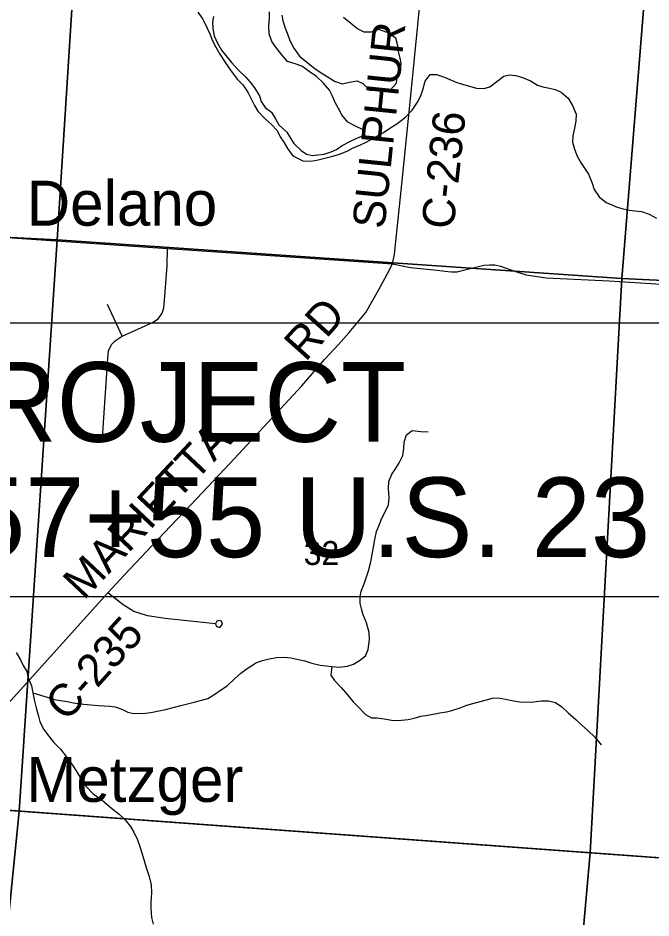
# Model space of a CAD drawing. Extents: x 0 to 34, y 0 to 22.
# Drawn here: x 6.672 to 7.784, y 18.22 to 19.8 of the extents above; entities that cross this region are included whole.
import ezdxf

# ---------------------------------------------------------------- set-up
doc = ezdxf.new("R2010")
doc.units = 0
for name, color, linetype in [('GM_X_Corporation', 7, 'Continuous'), ('GM_X_County_Road', 7, 'Continuous'), ('GM_X_County_Road_Text', 7, 'Continuous'), ('GM_X_Minor_Lake', 7, 'Continuous'), ('GM_X_Minor_River', 7, 'Continuous'), ('GM_X_Section_Text', 7, 'Continuous'), ('GM_X_Township_Road', 7, 'Continuous'), ('GM_X_Unincorporated_Text', 7, 'Continuous'), ('SH_Text', 7, 'Continuous')]:
    doc.layers.add(name, color=color, linetype=linetype)

msp = doc.modelspace()

# ---------------------------------------------------------------- linework, layer by layer
at = {"layer": 'GM_X_Corporation'}
for points in [[(5.8125, 20.4147), (5.8133, 20.4283), (6.802, 20.3679), (6.741, 19.4109), (5.7537, 19.4608)], [(6.802, 20.3679), (7.8088, 20.2797), (7.7331, 19.3433), (6.741, 19.4109)], [(7.8088, 20.2797), (8.8059, 20.2218), (8.7529, 19.294), (7.7331, 19.3433)], [(5.7537, 19.4608), (6.741, 19.4109), (6.6744, 18.4075), (5.6796, 18.4816)], [(6.741, 19.4109), (7.7331, 19.3433), (7.6778, 18.3345), (6.6744, 18.4075)], [(7.7331, 19.3433), (8.7529, 19.294), (8.6957, 18.2606), (7.6778, 18.3345)], [(5.6796, 18.4816), (6.6744, 18.4075), (6.5737, 17.4057), (5.601, 17.4809)], [(6.6744, 18.4075), (7.6778, 18.3345), (7.5885, 17.3345), (6.5737, 17.4057)], [(7.6778, 18.3345), (8.6957, 18.2606), (8.5882, 17.2585), (7.5885, 17.3345)]]:
    msp.add_lwpolyline(points, close=True, dxfattribs=at)
for points in [[(8.9, 18.2459), (6.4848, 18.4217), (6.0623, 18.451), (6.0209, 18.4538), (5.9218, 18.4615), (5.8252, 18.4693), (5.7826, 18.4727), (5.7687, 18.4738), (5.7047, 18.479), (5.6707, 18.4817), (5.1903, 18.5127), (5.1284, 18.4671)], [(6.4848, 18.4217), (8.9, 18.2459)]]:
    msp.add_lwpolyline(points, dxfattribs=at)
at = {"layer": 'GM_X_County_Road'}
msp.add_line((7.2681, 19.265), (7.2835, 19.2833), dxfattribs=at)
for points in [[(7.3304, 19.3689), (7.3338, 19.386), (7.3468, 19.5088), (7.3626, 19.6642), (7.3815, 19.8538), (7.4091, 20.1111), (7.4196, 20.2137), (7.4445, 20.4597), (7.4584, 20.5745), (7.4672, 20.6478), (7.474, 20.7219), (7.4739, 20.7892), (7.4713, 20.8345), (7.4616, 20.8801), (7.4574, 20.9)], [(6.4885, 18.4248), (6.6139, 18.5525), (6.6769, 18.6211), (6.8299, 18.7909), (6.8595, 18.823), (6.9179, 18.8845), (6.9863, 18.9569), (7.0524, 19.0267), (7.1182, 19.0976), (7.1707, 19.1546), (7.211, 19.201), (7.2355, 19.2269), (7.254, 19.2481), (7.2835, 19.2833), (7.3058, 19.3225), (7.3211, 19.3507), (7.3304, 19.3689)], [(7.3304, 19.3689), (7.3619, 19.3621), (7.4086, 19.3579), (7.4272, 19.3554), (7.4341, 19.355), (7.444, 19.3549), (7.4573, 19.3582), (7.4905, 19.3662), (7.5008, 19.3673), (7.5099, 19.3672), (7.5201, 19.3648), (7.5448, 19.3559), (7.5652, 19.3496), (7.6002, 19.3443), (7.7112, 19.3388), (7.9024, 19.3267)]]:
    msp.add_lwpolyline(points, dxfattribs=at)
at = {"layer": 'GM_X_Minor_Lake'}
for points in [[(7.016, 19.8028), (7.0141, 19.7933), (7.0145, 19.7822), (7.0171, 19.7693), (7.0228, 19.7564), (7.0296, 19.7442), (7.0372, 19.7347), (7.0474, 19.7221), (7.0588, 19.7096), (7.0717, 19.6974), (7.08, 19.6875), (7.0876, 19.678), (7.0967, 19.6635), (7.0993, 19.6536), (7.1065, 19.6434), (7.1179, 19.635), (7.1244, 19.6232), (7.1304, 19.6129), (7.1444, 19.6), (7.1509, 19.5893), (7.1569, 19.5798), (7.1695, 19.5676), (7.1793, 19.5615), (7.1892, 19.5592), (7.1998, 19.56), (7.2101, 19.5615), (7.2226, 19.5653), (7.2321, 19.5694), (7.2416, 19.5766), (7.2553, 19.5838), (7.2667, 19.5888), (7.2793, 19.5941), (7.2789, 19.6039), (7.2652, 19.6104), (7.2516, 19.6177), (7.2414, 19.6306), (7.2353, 19.6413), (7.2296, 19.6523), (7.2247, 19.6633), (7.2194, 19.6736), (7.2092, 19.6861), (7.1966, 19.6976), (7.1837, 19.7063), (7.1709, 19.7158), (7.1591, 19.7197), (7.1458, 19.7239), (7.1356, 19.736), (7.125, 19.7494), (7.1185, 19.7593), (7.1136, 19.7729), (7.1129, 19.7862), (7.114, 19.7995), (7.1144, 19.8113)], [(7.1361, 19.8052), (7.1376, 19.7953), (7.1417, 19.7828), (7.1466, 19.7706), (7.15, 19.7611), (7.1569, 19.7474), (7.1671, 19.7333), (7.1796, 19.723), (7.1936, 19.7116), (7.2031, 19.7055), (7.2153, 19.6979), (7.2285, 19.6895), (7.2418, 19.6849), (7.2547, 19.6876), (7.268, 19.6898), (7.2779, 19.6856), (7.2904, 19.6735), (7.3007, 19.6731), (7.3136, 19.6723), (7.3261, 19.6738), (7.3375, 19.6859), (7.3383, 19.6962), (7.3444, 19.7095), (7.3452, 19.7205), (7.3437, 19.73), (7.341, 19.7418), (7.3395, 19.7513), (7.3361, 19.765), (7.3206, 19.7749), (7.3062, 19.7802), (7.2925, 19.7753), (7.2807, 19.7757), (7.2689, 19.7814), (7.2568, 19.7909), (7.2443, 19.8012)]]:
    msp.add_lwpolyline(points, dxfattribs=at)
at = {"layer": 'GM_X_Minor_River'}
for p, q in [((7.2733, 18.7725), (7.2733, 18.784)), ((7.2756, 18.763), (7.2733, 18.7725)), ((7.279, 18.7527), (7.2756, 18.763))]:
    msp.add_line(p, q, dxfattribs=at)
for points in [[(6.9883, 19.8104), (6.997, 19.7982), (7.0046, 19.7826), (7.0095, 19.7727), (7.0137, 19.7606), (7.0197, 19.7492), (7.0269, 19.737), (7.0345, 19.7252), (7.0425, 19.713), (7.0501, 19.7024), (7.058, 19.6925), (7.0675, 19.683), (7.0762, 19.6704), (7.0879, 19.6468), (7.0936, 19.6366), (7.1061, 19.624), (7.1175, 19.6133), (7.1274, 19.6031), (7.1327, 19.592), (7.1391, 19.5825), (7.1455, 19.5715), (7.1554, 19.5582), (7.1725, 19.5498), (7.1869, 19.549), (7.1994, 19.5516), (7.2158, 19.5554), (7.2257, 19.558), (7.2374, 19.5614), (7.2504, 19.5667), (7.2599, 19.572), (7.2743, 19.5777), (7.2842, 19.5823), (7.2998, 19.591), (7.3142, 19.5993), (7.3275, 19.608), (7.3378, 19.6145), (7.353, 19.6262), (7.3648, 19.6384), (7.3739, 19.6528), (7.3797, 19.6627), (7.3835, 19.6741), (7.3877, 19.6896), (7.3964, 19.701), (7.4074, 19.7014), (7.4215, 19.6968), (7.431, 19.6922), (7.4431, 19.6873), (7.4534, 19.6842), (7.4632, 19.6815), (7.4777, 19.6773), (7.491, 19.6765), (7.5012, 19.6796), (7.5138, 19.689), (7.5259, 19.6981), (7.5354, 19.7004), (7.5468, 19.6996), (7.5586, 19.6958), (7.5726, 19.6901), (7.5848, 19.6825), (7.5946, 19.6794), (7.6064, 19.6771), (7.6159, 19.6748), (7.6265, 19.6699), (7.6387, 19.6596), (7.6466, 19.6466), (7.6527, 19.6318), (7.6523, 19.6193), (7.65, 19.6067)], [(7.65, 19.6067), (7.6469, 19.5938), (7.6465, 19.5824), (7.6499, 19.5699), (7.6545, 19.5577), (7.6605, 19.5474), (7.6677, 19.5368), (7.6745, 19.5261), (7.681, 19.5105), (7.6847, 19.4991), (7.6935, 19.4862), (7.7056, 19.4767), (7.7158, 19.4721), (7.7253, 19.4683), (7.7356, 19.4652), (7.7462, 19.4633), (7.7561, 19.4621), (7.7678, 19.4606), (7.7815, 19.456), (7.7944, 19.4492)], [(6.6984, 18.6158), (6.7235, 18.6077), (6.7364, 18.6039), (6.747, 18.602), (6.7588, 18.6001), (6.769, 18.5982), (6.7876, 18.5958), (6.8002, 18.5947), (6.8138, 18.5935), (6.8237, 18.5927), (6.8336, 18.5923), (6.8431, 18.5912), (6.8549, 18.5866), (6.8651, 18.5816), (6.875, 18.579), (6.8959, 18.5797), (6.9057, 18.5808), (6.9198, 18.5838), (6.9312, 18.5861), (6.9449, 18.5895), (6.9585, 18.5933), (6.9703, 18.5963), (6.9817, 18.5989), (6.9927, 18.6023), (7.0057, 18.6057), (7.0163, 18.6118), (7.03, 18.6213), (7.0399, 18.6277), (7.0524, 18.6402), (7.0635, 18.6501), (7.0749, 18.6584), (7.0912, 18.6687), (7.1019, 18.6724), (7.1133, 18.6751), (7.1273, 18.6773), (7.1399, 18.6781), (7.1516, 18.6769), (7.1653, 18.6742), (7.1763, 18.6716), (7.1888, 18.6677), (7.2033, 18.6643), (7.2139, 18.6628), (7.2234, 18.6616), (7.2374, 18.6604), (7.2507, 18.6623), (7.2618, 18.6661), (7.2724, 18.6725), (7.2827, 18.6805), (7.2876, 18.6919), (7.2899, 18.7094), (7.2892, 18.7215), (7.2843, 18.7383), (7.279, 18.7527), (7.2756, 18.763), (7.2733, 18.7725), (7.2733, 18.7846), (7.2753, 18.7941), (7.2802, 18.8067), (7.2837, 18.8177), (7.2882, 18.8295), (7.2924, 18.8458), (7.2947, 18.8587), (7.2967, 18.8712), (7.2993, 18.8849), (7.3024, 18.8986), (7.3066, 18.91), (7.3116, 18.9225), (7.3184, 18.9354), (7.3234, 18.9457), (7.3242, 18.9582), (7.3234, 18.9746), (7.3238, 18.9867), (7.3292, 18.9993), (7.3353, 19.0091), (7.3421, 19.0194), (7.3486, 19.0323), (7.3501, 19.0448), (7.3505, 19.0555), (7.3547, 19.0684), (7.3646, 19.076), (7.3798, 19.0744), (7.3927, 19.074)], [(6.6689, 18.6861), (6.6765, 18.6732), (6.6814, 18.6637), (6.6875, 18.653), (6.6897, 18.6435), (6.6958, 18.6279)], [(7.2234, 18.6616), (7.2222, 18.6468), (7.2283, 18.6373), (7.24, 18.6247), (7.2514, 18.6118), (7.2613, 18.6), (7.2704, 18.5901), (7.2829, 18.5775), (7.2931, 18.5718), (7.303, 18.5714), (7.3159, 18.5699), (7.3322, 18.5668), (7.3459, 18.5675), (7.3577, 18.569), (7.3683, 18.5713), (7.3801, 18.5743), (7.3923, 18.5766), (7.4135, 18.5803), (7.4253, 18.5822), (7.4348, 18.5845), (7.4489, 18.5894), (7.4606, 18.5936), (7.4717, 18.5966), (7.4865, 18.6011), (7.5062, 18.6064), (7.5157, 18.6068), (7.5287, 18.6045), (7.5397, 18.6018), (7.5541, 18.5995), (7.5674, 18.5991), (7.5788, 18.5998), (7.5917, 18.6013), (7.6046, 18.6017), (7.6164, 18.5986), (7.6278, 18.591), (7.6388, 18.5803), (7.6524, 18.5689), (7.6634, 18.5579), (7.6733, 18.5495), (7.6858, 18.5377), (7.6971, 18.5244)], [(6.6958, 18.6279), (6.6984, 18.6158), (6.7014, 18.6009), (6.7041, 18.5891), (6.7082, 18.5747), (6.7105, 18.5652), (6.7169, 18.5519), (6.7264, 18.5397), (6.7347, 18.529), (6.7469, 18.5169), (6.7571, 18.5035), (6.7681, 18.4883), (6.7745, 18.4784), (6.7813, 18.467), (6.7916, 18.4514), (6.8041, 18.4385), (6.8204, 18.4271), (6.8363, 18.413), (6.85, 18.4023), (6.8595, 18.3935), (6.8697, 18.381), (6.8758, 18.3711), (6.8822, 18.3574), (6.8863, 18.3456), (6.8897, 18.3346), (6.8947, 18.319), (6.8977, 18.3091), (6.903, 18.2928), (6.9064, 18.2787), (6.9067, 18.2646), (6.9055, 18.2479), (6.9055, 18.2373), (6.9066, 18.2213), (6.91, 18.2095)]]:
    msp.add_lwpolyline(points, dxfattribs=at)
at = {"layer": 'GM_X_Township_Road'}
for p, q in [((6.8554, 19.242), (6.8294, 19.2976)), ((6.9066, 19.265), (6.91, 19.2665)), ((6.8573, 18.7703), (6.8392, 18.784)), ((6.876, 18.7585), (6.8573, 18.7703)), ((6.8997, 18.7506), (6.876, 18.7585)), ((6.9307, 18.746), (6.8997, 18.7506)), ((6.9749, 18.7415), (6.9307, 18.746)), ((7.0254, 18.7423), (7.0214, 18.7415)), ((7.0298, 18.7411), (7.0254, 18.7423))]:
    msp.add_line(p, q, dxfattribs=at)
for points in [[(6.3653, 19.4317), (6.4253, 19.4291), (6.6014, 19.4184), (6.9352, 19.3955), (7.3304, 19.3689)], [(6.8209, 19.0625), (6.8219, 19.0809), (6.8301, 19.2031), (6.8311, 19.216), (6.8363, 19.2269), (6.8427, 19.2334), (6.8554, 19.242), (6.8891, 19.257), (6.91, 19.2665), (6.9192, 19.273), (6.9253, 19.2819), (6.9284, 19.2918), (6.9304, 19.3119), (6.9342, 19.3652), (6.9352, 19.3955)], [(7.0192, 18.7366), (7.021, 18.7318), (7.027, 18.7303), (7.0314, 18.7359), (7.0298, 18.7411), (7.0254, 18.7423), (7.0214, 18.7415), (7.0192, 18.7367), (6.9749, 18.7415), (6.9307, 18.746), (6.8997, 18.7506), (6.876, 18.7585), (6.8573, 18.7703), (6.8299, 18.7909)]]:
    msp.add_lwpolyline(points, dxfattribs=at)
at = {"layer": 'SH_Text'}
for p, q in [((6.3343, 19.265), (6.7313, 19.265)), ((6.3343, 19.265), (6.7313, 19.265)), ((6.7313, 19.265), (6.8446, 19.265)), ((6.7313, 19.265), (6.8446, 19.265)), ((6.8446, 19.265), (6.9066, 19.265)), ((6.8446, 19.265), (6.9066, 19.265)), ((6.9066, 19.265), (7.1057, 19.265)), ((6.9066, 19.265), (7.1057, 19.265)), ((7.1057, 19.265), (7.4168, 19.265)), ((7.3049, 19.265), (7.4168, 19.265))]:
    msp.add_line(p, q, dxfattribs=at)
for points in [[(6.6994, 18.784), (5.9283, 18.784), (5.9283, 19.265), (5.945, 19.265)], [(7.4168, 19.265), (7.9364, 19.265), (7.9364, 18.784), (6.6994, 18.784)]]:
    msp.add_lwpolyline(points, dxfattribs=at)

# ---------------------------------------------------------------- texts
at = {"layer": 'GM_X_County_Road_Text'}
for s, rotation, p in [('SULPHUR', 84.1551, (7.3162, 19.4289)), ('C-236', 83.9621, (7.4374, 19.428)), ('RD', 48.1751, (7.1774, 19.1954)), ('MARIETTA', 46.7762, (6.788, 18.7768)), ('C-235', 47.9306, (6.7575, 18.563))]:
    msp.add_text(s, height=0.05682, rotation=rotation, dxfattribs=at).set_placement(p)
at = {"layer": 'GM_X_Section_Text'}
msp.add_text('32', height=0.04186, rotation=0, dxfattribs=at).set_placement((7.1743, 18.8401))
at = {"layer": 'GM_X_Unincorporated_Text'}
for s, p in [('Delano', (6.6876, 19.4358)), ('Metzger', (6.6868, 18.4241))]:
    msp.add_text(s, height=0.07898, rotation=0, dxfattribs=at).set_placement(p)
at = {"layer": 'SH_Text'}
for s, p in [('END PROJECT', (6.0332, 19.0563)), ('STA. 857+55 U.S. 23', (6.0086, 18.8538))]:
    msp.add_text(s, height=0.14, dxfattribs=at).set_placement(p)

doc.saveas('drawing.dxf')
